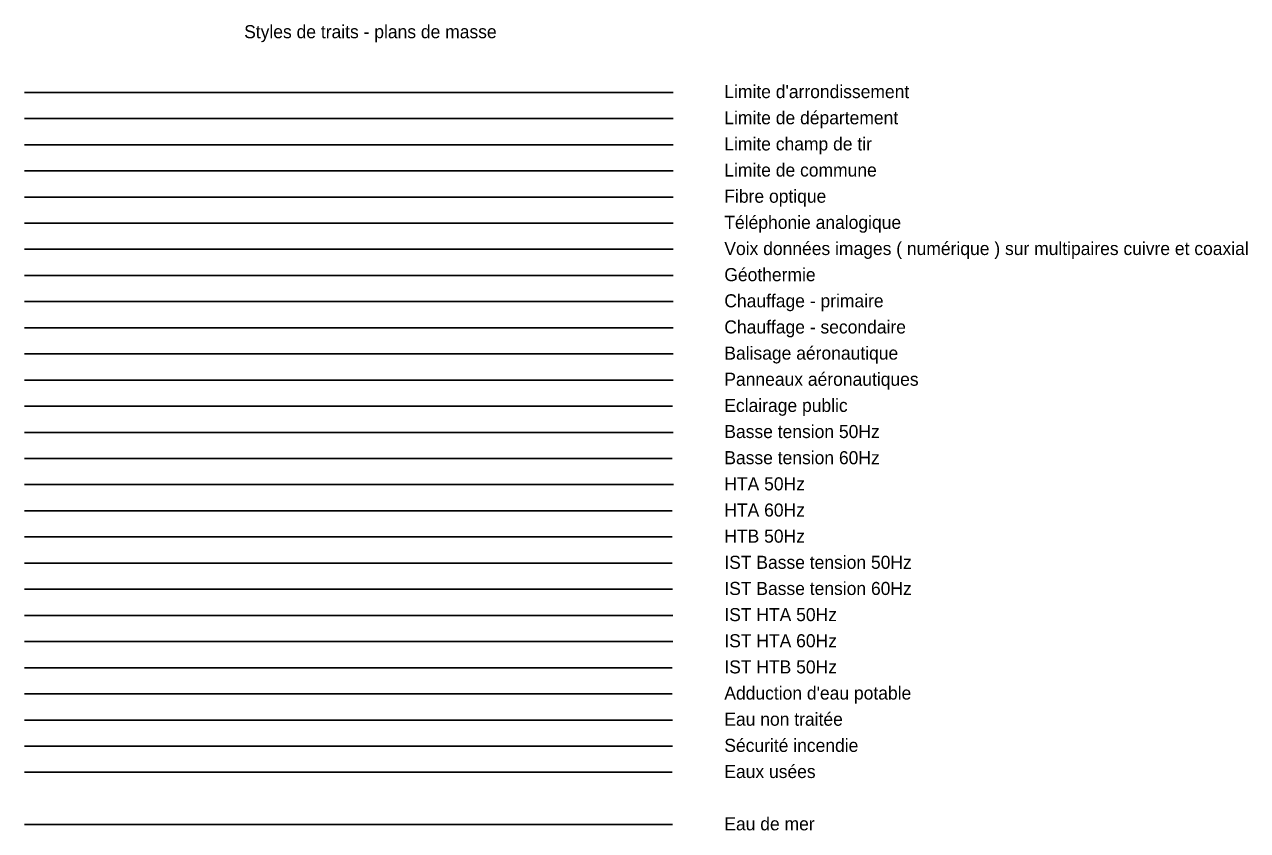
# Model space of a CAD drawing. Extents: x 3494.1 to 3554.6, y -18944.5 to -18883.7.
# Drawn here: x 3494.11 to 3540.92, y -18914.53 to -18883.71 of the extents above; entities that cross this region are included whole.
import ezdxf

# ---------------------------------------------------------------- set-up
doc = ezdxf.new("R2010")
doc.units = 0
for name, color, linetype in [('BAT_SID_AMIANTE_POLYLIGNE_TEXTE', 7, 'Continuous'), ('LIM_ADM ARRONDISSEMENT', 7, 'Continuous'), ('LIM_ADM DEPARTEMENT', 7, 'Continuous'), ('LIM_ADM_CHAMP TIR', 7, 'Continuous'), ('LIM_ADM_COMMUNE', 7, 'Continuous'), ('R_CF_TEL_LIAISON_CL_C', 7, 'Continuous'), ('R_CF_VDI_LIAISON_CL_C', 7, 'Continuous'), ('R_CH_GEOTHERMIE_CANALISATION_CL_C', 7, 'Continuous'), ('R_CH_PRIM_CANALISATION_CL_C', 7, 'Continuous'), ('R_CH_SECOND_CANALISATION_CL_C', 7, 'Continuous'), ('R_ECLAIR_AERO_LIAISON_CL_C', 7, 'Continuous'), ('R_ECLAIR_PANNEAU_AERO_LIAISON_CL_C', 7, 'Continuous'), ('R_ECLAIR_PUB_LIAISON_CL_C', 7, 'Continuous'), ('R_ELEC_BT_50HZ_LIAISON_CL_C', 7, 'Continuous'), ('R_ELEC_BT_60HZ_LIAISON_CL_C', 7, 'Continuous'), ('R_ELEC_HTA_50HZ_LIAISON_CL_C', 7, 'Continuous'), ('R_ELEC_HTA_60HZ_LIAISON_CL_C', 7, 'Continuous'), ('R_ELEC_HTB_50HZ_LIAISON_CL_C', 7, 'Continuous'), ('R_ELEC_IST_BT_50HZ_LIAISON_CL_C', 7, 'Continuous'), ('R_ELEC_IST_BT_60HZ_LIAISON_CL_C', 7, 'Continuous'), ('R_ELEC_IST_HTA_50HZ_LIAISON_CL_C', 7, 'Continuous'), ('R_ELEC_IST_HTA_60HZ_LIAISON_CL_C', 7, 'Continuous'), ('R_ELEC_IST_HTB_50HZ_LIAISON_CL_C', 7, 'Continuous'), ('R_EPR_AEP_CANALISATION_CL_C', 7, 'Continuous'), ('R_EPR_EAU_NON_TRAITEE_CANALISATION_CL_C', 7, 'Continuous'), ('R_EPR_INCENDIE_CANALISATION_CL_C', 7, 'Continuous'), ('R_ES_EU_CANALISATION_CL_C', 7, 'Continuous'), ('R_ES_MER_CANALISATION_CL_C', 7, 'Continuous'), ('SO_VMC_CVC_CTA_RES-TEXTE', 7, 'Continuous')]:
    doc.layers.add(name, color=color, linetype=linetype)

msp = doc.modelspace()

# ---------------------------------------------------------------- linework, layer by layer
at = {"layer": 'BAT_SID_AMIANTE_POLYLIGNE_TEXTE'}
msp.add_line((3494.112, -18890.308), (3518.932, -18890.308), dxfattribs=at)
at = {"layer": 'LIM_ADM ARRONDISSEMENT'}
msp.add_line((3494.112, -18886.308), (3518.932, -18886.308), dxfattribs=at)
at = {"layer": 'LIM_ADM DEPARTEMENT'}
msp.add_line((3494.112, -18887.308), (3518.932, -18887.308), dxfattribs=at)
at = {"layer": 'LIM_ADM_CHAMP TIR'}
msp.add_line((3494.112, -18888.308), (3518.932, -18888.308), dxfattribs=at)
at = {"layer": 'LIM_ADM_COMMUNE'}
msp.add_line((3494.112, -18889.308), (3518.932, -18889.308), dxfattribs=at)
at = {"layer": 'R_CF_TEL_LIAISON_CL_C'}
msp.add_line((3494.112, -18891.308), (3518.932, -18891.308), dxfattribs=at)
at = {"layer": 'R_CF_VDI_LIAISON_CL_C'}
msp.add_line((3494.112, -18892.308), (3518.932, -18892.308), dxfattribs=at)
at = {"layer": 'R_CH_GEOTHERMIE_CANALISATION_CL_C'}
msp.add_line((3494.112, -18893.308), (3518.932, -18893.308), dxfattribs=at)
at = {"layer": 'R_CH_PRIM_CANALISATION_CL_C'}
msp.add_line((3494.112, -18894.308), (3518.932, -18894.308), dxfattribs=at)
at = {"layer": 'R_CH_SECOND_CANALISATION_CL_C'}
msp.add_line((3494.112, -18895.308), (3518.932, -18895.308), dxfattribs=at)
at = {"layer": 'R_ECLAIR_AERO_LIAISON_CL_C'}
msp.add_line((3494.112, -18896.308), (3518.932, -18896.308), dxfattribs=at)
at = {"layer": 'R_ECLAIR_PANNEAU_AERO_LIAISON_CL_C'}
msp.add_line((3494.112, -18897.308), (3518.932, -18897.308), dxfattribs=at)
at = {"layer": 'R_ECLAIR_PUB_LIAISON_CL_C'}
msp.add_line((3494.112, -18898.308), (3518.912, -18898.308), dxfattribs=at)
at = {"layer": 'R_ELEC_BT_50HZ_LIAISON_CL_C'}
msp.add_line((3494.112, -18899.308), (3518.942, -18899.308), dxfattribs=at)
at = {"layer": 'R_ELEC_BT_60HZ_LIAISON_CL_C'}
msp.add_line((3494.112, -18900.308), (3518.905, -18900.308), dxfattribs=at)
at = {"layer": 'R_ELEC_HTA_50HZ_LIAISON_CL_C'}
msp.add_line((3494.112, -18901.308), (3518.95, -18901.308), dxfattribs=at)
at = {"layer": 'R_ELEC_HTA_60HZ_LIAISON_CL_C'}
msp.add_line((3494.112, -18902.308), (3518.905, -18902.308), dxfattribs=at)
at = {"layer": 'R_ELEC_HTB_50HZ_LIAISON_CL_C'}
msp.add_line((3494.112, -18903.304), (3518.905, -18903.304), dxfattribs=at)
at = {"layer": 'R_ELEC_IST_BT_50HZ_LIAISON_CL_C'}
msp.add_line((3494.112, -18904.308), (3518.897, -18904.308), dxfattribs=at)
at = {"layer": 'R_ELEC_IST_BT_60HZ_LIAISON_CL_C'}
msp.add_line((3494.112, -18905.308), (3518.912, -18905.308), dxfattribs=at)
at = {"layer": 'R_ELEC_IST_HTA_50HZ_LIAISON_CL_C'}
msp.add_line((3494.112, -18906.308), (3518.927, -18906.308), dxfattribs=at)
at = {"layer": 'R_ELEC_IST_HTA_60HZ_LIAISON_CL_C'}
msp.add_line((3494.112, -18907.308), (3518.927, -18907.308), dxfattribs=at)
at = {"layer": 'R_ELEC_IST_HTB_50HZ_LIAISON_CL_C'}
msp.add_line((3494.112, -18908.308), (3518.897, -18908.308), dxfattribs=at)
at = {"layer": 'R_EPR_AEP_CANALISATION_CL_C'}
msp.add_line((3494.112, -18909.308), (3518.897, -18909.308), dxfattribs=at)
at = {"layer": 'R_EPR_EAU_NON_TRAITEE_CANALISATION_CL_C'}
msp.add_line((3494.112, -18910.308), (3518.912, -18910.308), dxfattribs=at)
at = {"layer": 'R_EPR_INCENDIE_CANALISATION_CL_C'}
msp.add_line((3494.112, -18911.308), (3518.912, -18911.308), dxfattribs=at)
at = {"layer": 'R_ES_EU_CANALISATION_CL_C'}
msp.add_line((3494.112, -18912.308), (3518.897, -18912.308), dxfattribs=at)
at = {"layer": 'R_ES_MER_CANALISATION_CL_C'}
msp.add_line((3494.112, -18914.308), (3518.912, -18914.308), dxfattribs=at)

# ---------------------------------------------------------------- texts
at = {"layer": 'BAT_SID_AMIANTE_POLYLIGNE_TEXTE'}
msp.add_text('Fibre optique', height=0.5, dxfattribs=at).set_placement((3520.895, -18890.527))
at = {"layer": 'LIM_ADM ARRONDISSEMENT'}
msp.add_text("Limite d'arrondissement", height=0.5, dxfattribs=at).set_placement((3520.895, -18886.527))
at = {"layer": 'LIM_ADM DEPARTEMENT'}
msp.add_text('Limite de département', height=0.5, dxfattribs=at).set_placement((3520.895, -18887.527))
at = {"layer": 'LIM_ADM_CHAMP TIR'}
msp.add_text('Limite champ de tir', height=0.5, dxfattribs=at).set_placement((3520.895, -18888.527))
at = {"layer": 'LIM_ADM_COMMUNE'}
msp.add_text('Limite de commune', height=0.5, dxfattribs=at).set_placement((3520.895, -18889.527))
at = {"layer": 'R_CF_TEL_LIAISON_CL_C'}
msp.add_text('Téléphonie analogique', height=0.5, dxfattribs=at).set_placement((3520.895, -18891.527))
at = {"layer": 'R_CF_VDI_LIAISON_CL_C'}
msp.add_text('Voix données images ( numérique ) sur multipaires cuivre et coaxial', height=0.5, dxfattribs=at).set_placement((3520.895, -18892.527))
at = {"layer": 'R_CH_GEOTHERMIE_CANALISATION_CL_C'}
msp.add_text('Géothermie', height=0.5, dxfattribs=at).set_placement((3520.895, -18893.527))
at = {"layer": 'R_CH_PRIM_CANALISATION_CL_C'}
msp.add_text('Chauffage - primaire', height=0.5, dxfattribs=at).set_placement((3520.895, -18894.527))
at = {"layer": 'R_CH_SECOND_CANALISATION_CL_C'}
msp.add_text('Chauffage - secondaire ', height=0.5, dxfattribs=at).set_placement((3520.895, -18895.527))
at = {"layer": 'R_ECLAIR_AERO_LIAISON_CL_C'}
msp.add_text('Balisage aéronautique', height=0.5, dxfattribs=at).set_placement((3520.895, -18896.527))
at = {"layer": 'R_ECLAIR_PANNEAU_AERO_LIAISON_CL_C'}
msp.add_text('Panneaux aéronautiques', height=0.5, dxfattribs=at).set_placement((3520.895, -18897.527))
at = {"layer": 'R_ECLAIR_PUB_LIAISON_CL_C'}
msp.add_text('Eclairage public', height=0.5, dxfattribs=at).set_placement((3520.895, -18898.527))
at = {"layer": 'R_ELEC_BT_50HZ_LIAISON_CL_C'}
msp.add_text('Basse tension 50Hz', height=0.5, dxfattribs=at).set_placement((3520.895, -18899.527))
at = {"layer": 'R_ELEC_BT_60HZ_LIAISON_CL_C'}
msp.add_text('Basse tension 60Hz', height=0.5, dxfattribs=at).set_placement((3520.895, -18900.527))
at = {"layer": 'R_ELEC_HTA_50HZ_LIAISON_CL_C'}
msp.add_text('HTA 50Hz', height=0.5, dxfattribs=at).set_placement((3520.895, -18901.527))
at = {"layer": 'R_ELEC_HTA_60HZ_LIAISON_CL_C'}
msp.add_text('HTA 60Hz', height=0.5, dxfattribs=at).set_placement((3520.895, -18902.527))
at = {"layer": 'R_ELEC_HTB_50HZ_LIAISON_CL_C'}
msp.add_text('HTB 50Hz', height=0.5, dxfattribs=at).set_placement((3520.895, -18903.527))
at = {"layer": 'R_ELEC_IST_BT_50HZ_LIAISON_CL_C'}
msp.add_text('IST Basse tension 50Hz', height=0.5, dxfattribs=at).set_placement((3520.895, -18904.527))
at = {"layer": 'R_ELEC_IST_BT_60HZ_LIAISON_CL_C'}
msp.add_text('IST Basse tension 60Hz', height=0.5, dxfattribs=at).set_placement((3520.895, -18905.527))
at = {"layer": 'R_ELEC_IST_HTA_50HZ_LIAISON_CL_C'}
msp.add_text('IST HTA 50Hz', height=0.5, dxfattribs=at).set_placement((3520.895, -18906.527))
at = {"layer": 'R_ELEC_IST_HTA_60HZ_LIAISON_CL_C'}
msp.add_text('IST HTA 60Hz', height=0.5, dxfattribs=at).set_placement((3520.895, -18907.527))
at = {"layer": 'R_ELEC_IST_HTB_50HZ_LIAISON_CL_C'}
msp.add_text('IST HTB 50Hz', height=0.5, dxfattribs=at).set_placement((3520.895, -18908.527))
at = {"layer": 'R_EPR_AEP_CANALISATION_CL_C'}
msp.add_text("Adduction d'eau potable ", height=0.5, dxfattribs=at).set_placement((3520.895, -18909.527))
at = {"layer": 'R_EPR_EAU_NON_TRAITEE_CANALISATION_CL_C'}
msp.add_text('Eau non traitée', height=0.5, dxfattribs=at).set_placement((3520.895, -18910.527))
at = {"layer": 'R_EPR_INCENDIE_CANALISATION_CL_C'}
msp.add_text('Sécurité incendie', height=0.5, dxfattribs=at).set_placement((3520.895, -18911.527))
at = {"layer": 'R_ES_EU_CANALISATION_CL_C'}
msp.add_text('Eaux usées', height=0.5, dxfattribs=at).set_placement((3520.895, -18912.527))
at = {"layer": 'R_ES_MER_CANALISATION_CL_C'}
msp.add_text('Eau de mer', height=0.5, dxfattribs=at).set_placement((3520.895, -18914.527))
at = {"layer": 'SO_VMC_CVC_CTA_RES-TEXTE'}
msp.add_text('Styles de traits - plans de masse', height=0.5, dxfattribs=at).set_placement((3502.52, -18884.237))

doc.saveas('drawing.dxf')
